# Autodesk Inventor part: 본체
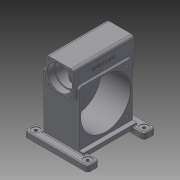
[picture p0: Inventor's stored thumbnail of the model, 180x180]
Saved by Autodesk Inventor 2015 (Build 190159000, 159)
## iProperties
Created: 2025-06
Part Number: 본체
Material: 일반
Document SubType Name: Modeling
Designer: 104
Density: 1 g/cm^3
Appearance: 기본값
Mass: 2964.23 g
Surface Area: 3446.05 cm^2
Volume: 2964.23 cm^3
Author: 104
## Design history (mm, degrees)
sketch "스케치1"
  geometry: L1 (-93, -103)-(93, -103); L2 (93, -103)-(93, 103); L3 (93, 103)-(-93, 103); L4 (-93, 103)-(-93, -103); L5 (-93, -103)-(93, 103); L6 (93, -103)-(-93, 103); 1 further point
  constraints: 12 end point, 2 midpoint, 2 parallel, 1 horizontal, 1 perpendicular
  dimensions: "d0" = 186 distance of L3.end L2.end; "d1" = 206 distance of L2.end L1.end
extrude "돌출1" new body sketch "스케치1" distance "d2" = 140; taper "d3" = 0 deg
sketch "스케치2"
  geometry: L1 (140, 206)-(125, 206); L2 (125, 206)-(125, 17); L3 (125, 17)-(140, 17); L4 (140, 17)-(140, 206); 1 further point
  constraints: 8 end point, 2 parallel, 1 horizontal, 1 perpendicular
  dimensions: "d4" = 15 distance of L3.end L2.end; "d5" = 189 distance of L2.end L1.end
extrude "돌출2" cut sketch "스케치2" stored distance "d6" = 140; taper "d7" = 0 deg
node "작업 평면1"
sketch "스케치3"
  geometry: L1 (-140, -86)-(-125, -86) reference; L2 (-125, -86)-(-125, 103) reference; L3 (0, 103)-(-125, 103) reference; L4 (0, 103)-(0, -103) reference; L5 (0, -103)-(-140, -103) reference; L6 (-140, -86)-(-140, -103) reference; L7 (-22, 158)-(-118, 158); L8 (-118, 158)-(-118, 62); L9 (-118, 62)-(-22, 62); L10 (-22, 62)-(-22, 158); 3 further points
  constraints: 8 end point, 2 midpoint, 2 parallel, 1 horizontal, 1 perpendicular, 1 vertical alignment
  dimensions: "d9" = 96 distance of L7.start L7.end; "d10" = 96 distance of L7.end L8.end; "d11" = 55 distance between parallel lines of L7 L3
extrude "돌출3" join sketch "스케치3" distance "d12" = 210; taper "d13" = 0 deg
sketch "스케치4"
  geometry: L1 (118, 62)-(22, 62) reference; L2 (118, 158)-(118, 62) reference; C1 r 42.5 at (70, 110); 3 further points
  constraints: 2 midpoint, 1 centre point, 1 horizontal alignment, 1 vertical alignment
  dimensions: "d14" = 85 diameter of C1
extrude "돌출4" cut sketch "스케치4" distance "d15" = 23; taper "d16" = 0 deg
sketch "스케치5"
  geometry: C1 r 42.5 at (0, 0) reference; C2 r 38.5 at (0, 0); 1 further point
  constraints: 1 centre point, 1 coincident
  dimensions: "d17" = 77 diameter of C2
extrude "돌출5" cut sketch "스케치5" stored distance "d18" = 23; taper "d19" = 0 deg
node "작업 평면2"
sketch "스케치7"
  geometry: L1 (158, -13)-(-62, -13); L2 (-62, -13)-(-62, 27); L3 (-62, 27)-(158, 27); L4 (158, 27)-(158, -13); L5 (96, 0)-(0, 0) reference; L6 (158, 223)-(-62, 223); L7 (-62, 223)-(-62, 183); L8 (-62, 183)-(158, 183); L9 (158, 183)-(158, 223); L10 (96, 210)-(0, 210) reference; 5 further points
  constraints: 16 end point, 4 midpoint, 4 parallel, 2 horizontal, 2 perpendicular, 2 vertical alignment
  dimensions: "d26" = 220 distance of L2.end L3.end; "d27" = 40 distance of L1.end L2.end; "d28" = 118 distance from line of L1 point (-22, 105); "d29" = 220 distance of L8.end L7.end; "d30" = 40 distance of L7.end L6.end; "d31" = 118 distance from line of L6 point (-22, 105)
extrude "돌출6" join sketch "스케치7" distance "d32" = 20; taper "d33" = 0 deg
sketch "스케치8"
  geometry: L1 (216, 171)-(216, 211) reference; C1 r 86 at (93, 93); 1 further point
  constraints: 1 centre point, 1 horizontal alignment
  dimensions: "d34" = 172 diameter of C1; "d35" = 123 distance from line of L1 C1.centre
extrude "돌출7" cut sketch "스케치8" distance "d36" = 102; taper "d37" = 0 deg
sketch "스케치9"
  geometry: C1 r 86 at (0, 0) reference; 1 further point
hole "구멍1" sketch "스케치9" at (0, 0) diameter "d38" = 62; stored, may be unused: countersink angle "d42" = 90 deg, drill point angle "d44" = 0 deg; dims "d39" = 6, "d40" = 4, "d41" = 2, "d43" = 16
sketch "스케치10"
  geometry: C1 r 31 at (0, 0) reference; 1 further point
hole "구멍2" sketch "스케치10" at (0, 0) diameter "d45" = 54; stored, may be unused: countersink angle "d49" = 90 deg, drill point angle "d51" = 0 deg; dims "d46" = 6, "d47" = 4, "d48" = 2, "d50" = 3
fillet "모깎기1" dims "d52" = 1
fillet "모깎기2" dims "d53" = 10
sketch "스케치11"
  geometry: L1 (148, 223)-(-52, 223) reference; L2 (-62, -3)-(-62, 17) reference; L3 (-52, 27)-(148, 27) reference; L4 (158, 17)-(158, -3) reference; L5 (148, -13)-(-52, -13) reference; L6 (-42, 7)-(138, 7); L7 (138, 7)-(138, 203); L8 (138, 203)-(-42, 203); L9 (-42, 203)-(-42, 7); L10 (148, -13)-(-52, -13) reference; L11 (48, -13)-(48, 223); A1 r 10 centre (-52, -3) between (-62, -3) and (-52, -13) reference; A2 r 10 centre (148, -3) between (148, -13) and (158, -3) reference; A3 r 10 centre (148, 17) between (158, 17) and (148, 27) reference; A4 r 10 centre (-52, 17) between (-52, 27) and (-62, 17) reference; 4 further points
  constraints: 10 end point, 5 midpoint, 2 parallel, 2 perpendicular, 1 horizontal, 1 horizontal alignment, 1 vertical alignment
  dimensions: "d54" = 180 distance of L8.end L7.end; "d55" = 196 distance of L7.end L6.end
hole "구멍3" sketch "스케치11" at (138, 7), (138, 203), (-42, 7), (-42, 203) diameter "d56" = 11; stored, may be unused: countersink angle "d60" = 90 deg, drill point angle "d62" = 0 deg; dims "d57" = 6, "d58" = 28, "d59" = 2, "d61" = 3
sketch "스케치12"
  geometry: L1 (18, 18)-(168, 18); L2 (168, 18)-(168, 168); L3 (168, 168)-(18, 168); L4 (18, 168)-(18, 18); C1 r 86 at (93, 93) reference; 3 further points
  constraints: 8 end point, 2 midpoint, 2 parallel, 1 horizontal, 1 horizontal alignment, 1 perpendicular, 1 vertical alignment
  dimensions: "d63" = 150 distance of L3.end L2.end; "d64" = 150 distance of L2.end L1.end
hole "구멍4" sketch "스케치12" at (18, 18), (18, 168), (168, 168), (168, 18) diameter "d65" = 6.647; stored, may be unused: countersink angle "d69" = 90 deg, drill point angle "d71" = 118 deg; dims "d66" = 16, "d67" = 28, "d68" = 2, "d70" = 18
sketch "스케치13"
  geometry: L1 (22, 158)-(118, 158) reference; L2 (32, 148)-(108, 148); L3 (108, 148)-(108, 72); L4 (108, 72)-(32, 72); L5 (32, 72)-(32, 148); C1 r 42.5 at (70, 110) reference; 4 further points
  constraints: 8 end point, 3 midpoint, 2 parallel, 1 horizontal, 1 horizontal alignment, 1 perpendicular, 1 vertical alignment
  dimensions: "d72" = 76 distance of L3.end L4.end; "d73" = 76 distance of L2.end L3.end
hole "구멍5" sketch "스케치13" at (108, 148), (32, 148), (32, 72), (108, 72) diameter "d74" = 4.917; stored, may be unused: countersink angle "d78" = 90 deg, drill point angle "d80" = 118 deg; dims "d75" = 12, "d76" = 28, "d77" = 2, "d79" = 14
node "작업 평면3"
fillet "모깎기3" dims "d81" = 3
fillet "모깎기4" dims "d82" = 3
fillet "모깎기5" dims "d83" = 3
fillet "모깎기9" dims "d87" = 1.1
sketch "스케치14"
  geometry: L1 (-10, 210)-(-10, 0) reference; 3 further points
  constraints: 1 horizontal alignment, 1 midpoint, 1 other
  dimensions: "d88" = 30 distance from line of point (20, 105) L1
feature "엠보싱1" sketch "스케치14" dims "d89" = 0.5, "d90" = 0
fillet "모깎기10" dims "d91" = 3
chamfer "모따기1" distance "d92" = 1; stored, may be unused: second distance "d93" = 2, angle "d94" = 45 deg
chamfer "모따기2" distance "d95" = 1; stored, may be unused: second distance "d96" = 2, angle "d97" = 45 deg
fillet "모깎기11" dims "d98" = 3
fillet "모깎기13" dims "d100" = 3
fillet "모깎기14" dims "d101" = 3
chamfer "모따기3" distance "d102" = 1; stored, may be unused: second distance "d103" = 2, angle "d104" = 45 deg
fillet "모깎기15" dims "d105" = 10
fillet "모깎기16" dims "d106" = 3
node "솔리드1"
mirror "대칭1"
mirror "대칭2"
node "투영된 루프1"
node "투영된 루프3"
other parameters: "d8" = -105, "d25" = -271
